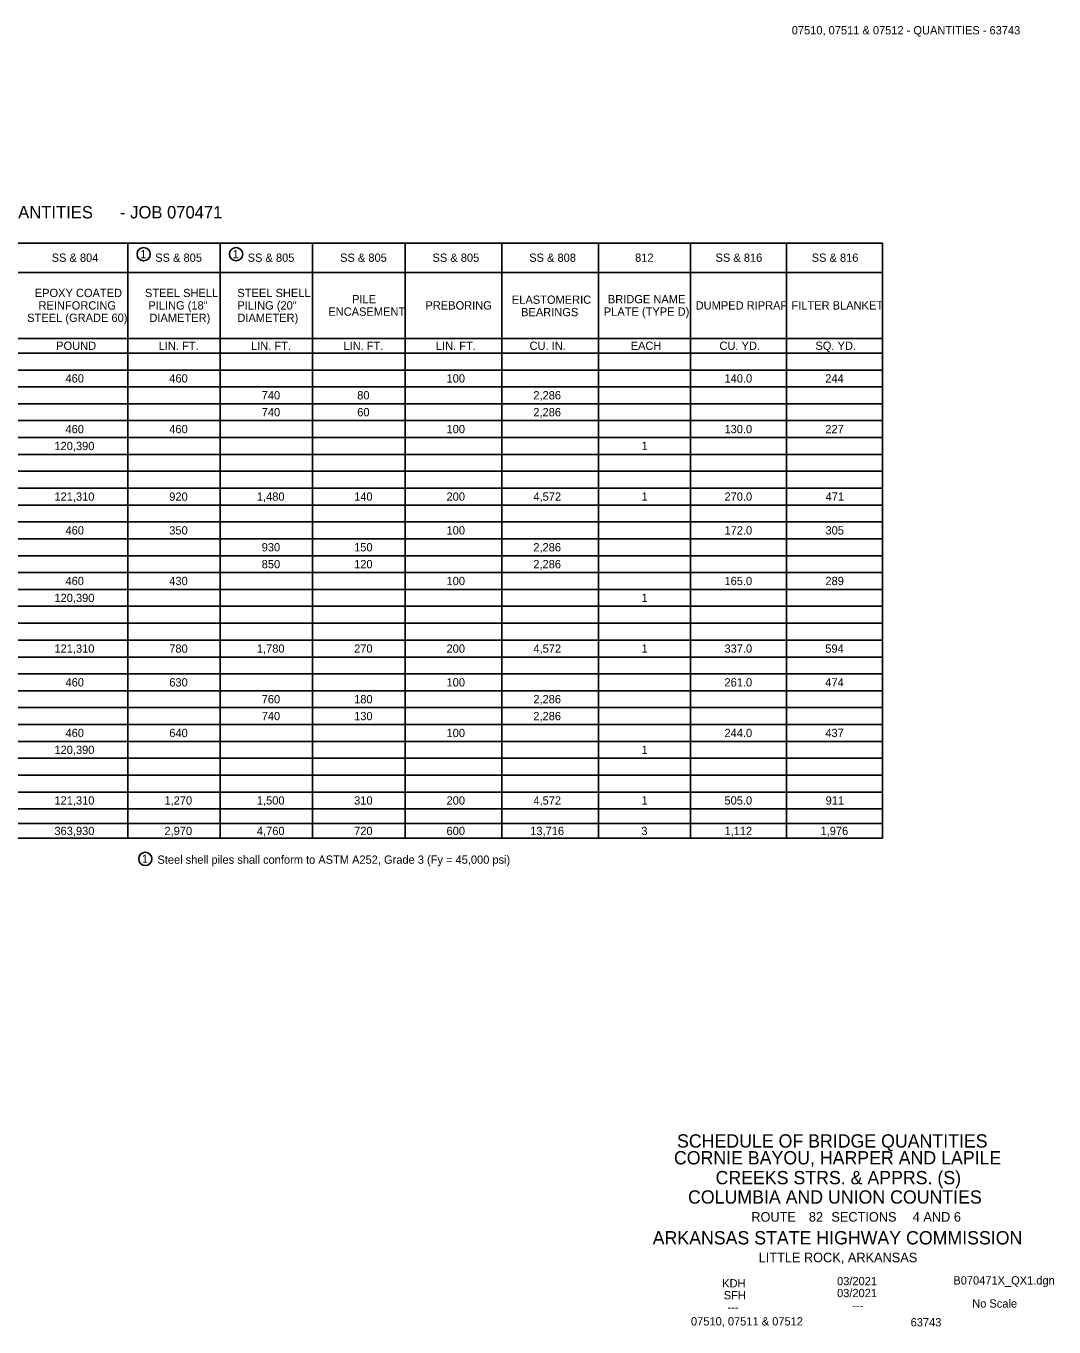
# Model space of a CAD drawing. Extents: x 978208 to 1610025, y 186514 to 1526540.
# Drawn here: x 978221.92 to 978237.45, y 1526241.85 to 1526261.49 of the extents above; entities that cross this region are included whole.
import ezdxf

# ---------------------------------------------------------------- set-up
doc = ezdxf.new("R2010")
doc.units = 0
for name, color, linetype in [('B_Copy In', 7, 'Continuous'), ('B_County and Route', 7, 'Continuous'), ('B_Text', 7, 'Continuous'), ('B_Title Text', 7, 'Continuous')]:
    doc.layers.add(name, color=color, linetype=linetype)

msp = doc.modelspace()

# ---------------------------------------------------------------- linework, layer by layer
at = {"layer": 'B_Text'}
for p, q in [((978207.713, 1526258.214), (978234.856, 1526258.214)), ((978223.454, 1526249.229), (978223.454, 1526258.214)), ((978224.85, 1526249.229), (978224.85, 1526258.214)), ((978226.246, 1526249.229), (978226.246, 1526258.214)), ((978227.643, 1526249.229), (978227.643, 1526258.214)), ((978229.105, 1526249.229), (978229.105, 1526258.214)), ((978230.568, 1526249.229), (978230.568, 1526258.214)), ((978231.953, 1526249.229), (978231.953, 1526258.214)), ((978233.404, 1526249.229), (978233.404, 1526258.214)), ((978234.856, 1526249.229), (978234.856, 1526258.214)), ((978211.886, 1526257.771), (978234.856, 1526257.771)), ((978211.886, 1526256.774), (978234.856, 1526256.774)), ((978207.713, 1526256.552), (978234.856, 1526256.552)), ((978209.131, 1526256.297), (978234.856, 1526256.297)), ((978209.131, 1526256.043), (978234.856, 1526256.043)), ((978209.131, 1526255.788), (978234.856, 1526255.788)), ((978209.131, 1526255.533), (978234.856, 1526255.533)), ((978209.131, 1526255.278), (978234.856, 1526255.278)), ((978209.131, 1526255.023), (978234.856, 1526255.023)), ((978209.131, 1526254.768), (978234.856, 1526254.768)), ((978207.713, 1526254.514), (978234.856, 1526254.514)), ((978207.713, 1526254.259), (978234.856, 1526254.259)), ((978209.131, 1526254.004), (978234.856, 1526254.004)), ((978209.131, 1526253.749), (978234.856, 1526253.749)), ((978209.131, 1526253.494), (978234.856, 1526253.494)), ((978209.131, 1526253.239), (978234.856, 1526253.239)), ((978209.131, 1526252.985), (978234.856, 1526252.985)), ((978209.131, 1526252.73), (978234.856, 1526252.73)), ((978209.131, 1526252.475), (978234.856, 1526252.475)), ((978207.713, 1526252.22), (978234.856, 1526252.22)), ((978207.713, 1526251.965), (978234.856, 1526251.965)), ((978209.131, 1526251.71), (978234.856, 1526251.71)), ((978209.131, 1526251.456), (978234.856, 1526251.456)), ((978209.131, 1526251.201), (978234.856, 1526251.201)), ((978209.131, 1526250.946), (978234.856, 1526250.946)), ((978209.131, 1526250.691), (978234.856, 1526250.691)), ((978209.131, 1526250.436), (978234.856, 1526250.436)), ((978209.131, 1526250.181), (978234.856, 1526250.181)), ((978207.713, 1526249.927), (978234.856, 1526249.927)), ((978207.713, 1526249.672), (978234.856, 1526249.672)), ((978207.713, 1526249.45), (978234.856, 1526249.45)), ((978207.713, 1526249.229), (978234.856, 1526249.229))]:
    msp.add_line(p, q, dxfattribs=at)
for centre in [(978223.695, 1526258.045), (978225.091, 1526258.045), (978223.72, 1526248.917)]:
    msp.add_circle(centre, 0.1, dxfattribs=at)

# ---------------------------------------------------------------- texts
at = {"layer": 'B_Copy In'}
for s, height, p in [('07510, 07511 & 07512 - QUANTITIES - 63743', 0.1248, (978233.485, 1526261.363)), ('SCHEDULE OF BRIDGE QUANTITIES', 0.2004, (978231.752, 1526244.56)), ('CORNIE BAYOU, HARPER AND LAPILE ', 0.2004, (978231.705, 1526244.306)), ('CREEKS STRS. & APPRS. (S)', 0.2004, (978232.334, 1526244.006)), ('KDH', 0.1248, (978232.434, 1526242.449)), ('03/2021', 0.1248, (978234.169, 1526242.482)), ('B070471X_QX1.dgn', 0.1248, (978235.926, 1526242.493)), ('SFH', 0.1248, (978232.457, 1526242.269)), ('03/2021', 0.1248, (978234.169, 1526242.302)), ('---', 0.1248, (978234.399, 1526242.115)), ('No Scale', 0.1248, (978236.211, 1526242.144)), ('07510, 07511 & 07512 ', 0.125, (978231.962, 1526241.875)), ('---', 0.1248, (978232.512, 1526242.089)), ('63743', 0.125, (978235.28, 1526241.861))]:
    msp.add_text(s, height=height, dxfattribs=at).set_placement(p)
at = {"layer": 'B_County and Route'}
for s, height, p in [('COLUMBIA AND UNION COUNTIES', 0.2004, (978231.918, 1526243.714)), ('82', 0.144, (978233.743, 1526243.442)), ('4 AND 6', 0.144, (978235.312, 1526243.442))]:
    msp.add_text(s, height=height, dxfattribs=at).set_placement(p)
at = {"layer": 'B_Text'}
for s, height, p in [('SCHEDULE OF BRIDGE QUANTITIES', 0.1875, (978218.54, 1526258.585)), (' - JOB 070471', 0.1875, (978223.268, 1526258.585)), ('SS & 804', 0.125, (978222.305, 1526257.93)), ('1', 0.125, (978223.642, 1526257.983)), ('SS & 805', 0.125, (978223.87, 1526257.93)), ('1', 0.125, (978225.038, 1526257.983)), ('SS & 805', 0.125, (978225.266, 1526257.93)), ('SS & 805', 0.125, (978226.662, 1526257.93)), ('SS & 805', 0.125, (978228.058, 1526257.93)), ('SS & 808', 0.125, (978229.519, 1526257.93)), ('812', 0.125, (978231.118, 1526257.93)), ('SS & 816', 0.125, (978232.333, 1526257.93)), ('SS & 816', 0.125, (978233.785, 1526257.93)), ('EPOXY COATED', 0.125, (978222.05, 1526257.398)), ('STEEL SHELL', 0.125, (978223.715, 1526257.398)), ('STEEL SHELL', 0.125, (978225.111, 1526257.398)), ('REINFORCING', 0.125, (978222.107, 1526257.21)), ('PILING (18"', 0.125, (978223.766, 1526257.21)), ('PILING (20"', 0.125, (978225.111, 1526257.21)), ('PILE', 0.125, (978226.843, 1526257.304)), ('PREBORING', 0.125, (978227.951, 1526257.21)), ('ELASTOMERIC', 0.125, (978229.257, 1526257.296)), ('BRIDGE NAME', 0.125, (978230.707, 1526257.304)), ('DUMPED RIPRAP', 0.125, (978232.033, 1526257.21)), ('FILTER BLANKET', 0.125, (978233.48, 1526257.21)), ('STEEL (GRADE 60)', 0.125, (978221.936, 1526257.023)), ('DIAMETER)', 0.125, (978223.782, 1526257.023)), ('DIAMETER)', 0.125, (978225.111, 1526257.023)), ('ENCASEMENT', 0.125, (978226.484, 1526257.116)), ('   BEARINGS', 0.125, (978229.257, 1526257.109)), ('PLATE (TYPE D)', 0.125, (978230.646, 1526257.116)), ('POUND', 0.125, (978222.373, 1526256.601)), ('LIN. FT.', 0.125, (978223.921, 1526256.601)), ('LIN. FT.', 0.125, (978225.317, 1526256.601)), ('LIN. FT.', 0.125, (978226.713, 1526256.601)), ('LIN. FT.', 0.125, (978228.109, 1526256.601)), ('CU. IN.', 0.125, (978229.524, 1526256.601)), ('EACH', 0.125, (978231.051, 1526256.601)), ('CU. YD.', 0.125, (978232.392, 1526256.601)), ('SQ. YD.', 0.125, (978233.842, 1526256.601)), ('460', 0.125, (978222.514, 1526256.108)), ('460', 0.125, (978224.082, 1526256.108)), ('100', 0.125, (978228.27, 1526256.108)), ('140.0', 0.125, (978232.468, 1526256.108)), ('244', 0.125, (978233.991, 1526256.108)), ('740', 0.125, (978225.478, 1526255.853)), ('80', 0.125, (978226.921, 1526255.853)), ('2,286', 0.125, (978229.581, 1526255.853)), ('740', 0.125, (978225.478, 1526255.598)), ('60', 0.125, (978226.921, 1526255.598)), ('2,286', 0.125, (978229.581, 1526255.598)), ('460', 0.125, (978222.514, 1526255.343)), ('460', 0.125, (978224.082, 1526255.343)), ('100', 0.125, (978228.27, 1526255.343)), ('130.0', 0.125, (978232.468, 1526255.343)), ('227', 0.125, (978233.992, 1526255.343)), ('120,390', 0.125, (978222.347, 1526255.088)), ('1', 0.125, (978231.215, 1526255.088)), ('121,310', 0.125, (978222.347, 1526254.324)), ('920', 0.125, (978224.082, 1526254.324)), ('1,480', 0.125, (978225.405, 1526254.324)), ('140', 0.125, (978226.874, 1526254.324)), ('200', 0.125, (978228.27, 1526254.324)), ('4,572', 0.125, (978229.582, 1526254.324)), ('1', 0.125, (978231.215, 1526254.324)), ('270.0', 0.125, (978232.468, 1526254.324)), ('471', 0.125, (978233.996, 1526254.324)), ('460', 0.125, (978222.514, 1526253.814)), ('350', 0.125, (978224.082, 1526253.814)), ('100', 0.125, (978228.27, 1526253.814)), ('172.0', 0.125, (978232.468, 1526253.814)), ('305', 0.125, (978233.994, 1526253.814)), ('930', 0.125, (978225.478, 1526253.559)), ('150', 0.125, (978226.874, 1526253.559)), ('2,286', 0.125, (978229.581, 1526253.559)), ('850', 0.125, (978225.478, 1526253.304)), ('120', 0.125, (978226.874, 1526253.304)), ('2,286', 0.125, (978229.581, 1526253.304)), ('460', 0.125, (978222.514, 1526253.05)), ('430', 0.125, (978224.082, 1526253.05)), ('100', 0.125, (978228.27, 1526253.05)), ('165.0', 0.125, (978232.468, 1526253.05)), ('289', 0.125, (978233.993, 1526253.05)), ('120,390', 0.125, (978222.347, 1526252.795)), ('1', 0.125, (978231.215, 1526252.795)), ('121,310', 0.125, (978222.347, 1526252.03)), ('780', 0.125, (978224.082, 1526252.03)), ('1,780', 0.125, (978225.405, 1526252.03)), ('270', 0.125, (978226.874, 1526252.03)), ('200', 0.125, (978228.27, 1526252.03)), ('4,572', 0.125, (978229.582, 1526252.03)), ('1', 0.125, (978231.215, 1526252.03)), ('337.0', 0.125, (978232.468, 1526252.03)), ('594', 0.125, (978233.991, 1526252.03)), ('460', 0.125, (978222.514, 1526251.52)), ('630', 0.125, (978224.082, 1526251.52)), ('100', 0.125, (978228.27, 1526251.52)), ('261.0', 0.125, (978232.468, 1526251.52)), ('474', 0.125, (978233.991, 1526251.52)), ('760', 0.125, (978225.478, 1526251.266)), ('180', 0.125, (978226.874, 1526251.266)), ('2,286', 0.125, (978229.581, 1526251.266)), ('740', 0.125, (978225.478, 1526251.011)), ('130', 0.125, (978226.874, 1526251.011)), ('2,286', 0.125, (978229.581, 1526251.011)), ('460', 0.125, (978222.514, 1526250.756)), ('640', 0.125, (978224.082, 1526250.756)), ('100', 0.125, (978228.27, 1526250.756)), ('244.0', 0.125, (978232.468, 1526250.756)), ('437', 0.125, (978233.992, 1526250.756)), ('120,390', 0.125, (978222.347, 1526250.501)), ('1', 0.125, (978231.215, 1526250.501)), ('121,310', 0.125, (978222.347, 1526249.737)), ('1,270', 0.125, (978224.009, 1526249.737)), ('1,500', 0.125, (978225.405, 1526249.737)), ('310', 0.125, (978226.874, 1526249.737)), ('200', 0.125, (978228.27, 1526249.737)), ('4,572', 0.125, (978229.582, 1526249.737)), ('1', 0.125, (978231.215, 1526249.737)), ('505.0', 0.125, (978232.468, 1526249.737)), ('911', 0.125, (978233.996, 1526249.737)), ('363,930', 0.125, (978222.347, 1526249.277)), ('2,970', 0.125, (978224.009, 1526249.277)), ('4,760', 0.125, (978225.405, 1526249.277)), ('720', 0.125, (978226.874, 1526249.277)), ('600', 0.125, (978228.27, 1526249.277)), ('13,716', 0.125, (978229.534, 1526249.277)), ('3', 0.125, (978231.213, 1526249.277)), ('1,112', 0.125, (978232.468, 1526249.277)), ('1,976', 0.125, (978233.919, 1526249.277)), ('1', 0.125, (978223.667, 1526248.854)), ('Steel shell piles shall conform to ASTM A252, Grade 3 (Fy = 45,000 psi)', 0.1248, (978223.903, 1526248.844))]:
    msp.add_text(s, height=height, dxfattribs=at).set_placement(p)
at = {"layer": 'B_Title Text'}
for s, height, p in [('ROUTE          SECTIONS ', 0.144, (978232.874, 1526243.442)), ('ARKANSAS STATE HIGHWAY COMMISSION', 0.2004, (978231.384, 1526243.098)), ('LITTLE ROCK, ARKANSAS', 0.144, (978232.984, 1526242.829))]:
    msp.add_text(s, height=height, dxfattribs=at).set_placement(p)

doc.saveas('drawing.dxf')
